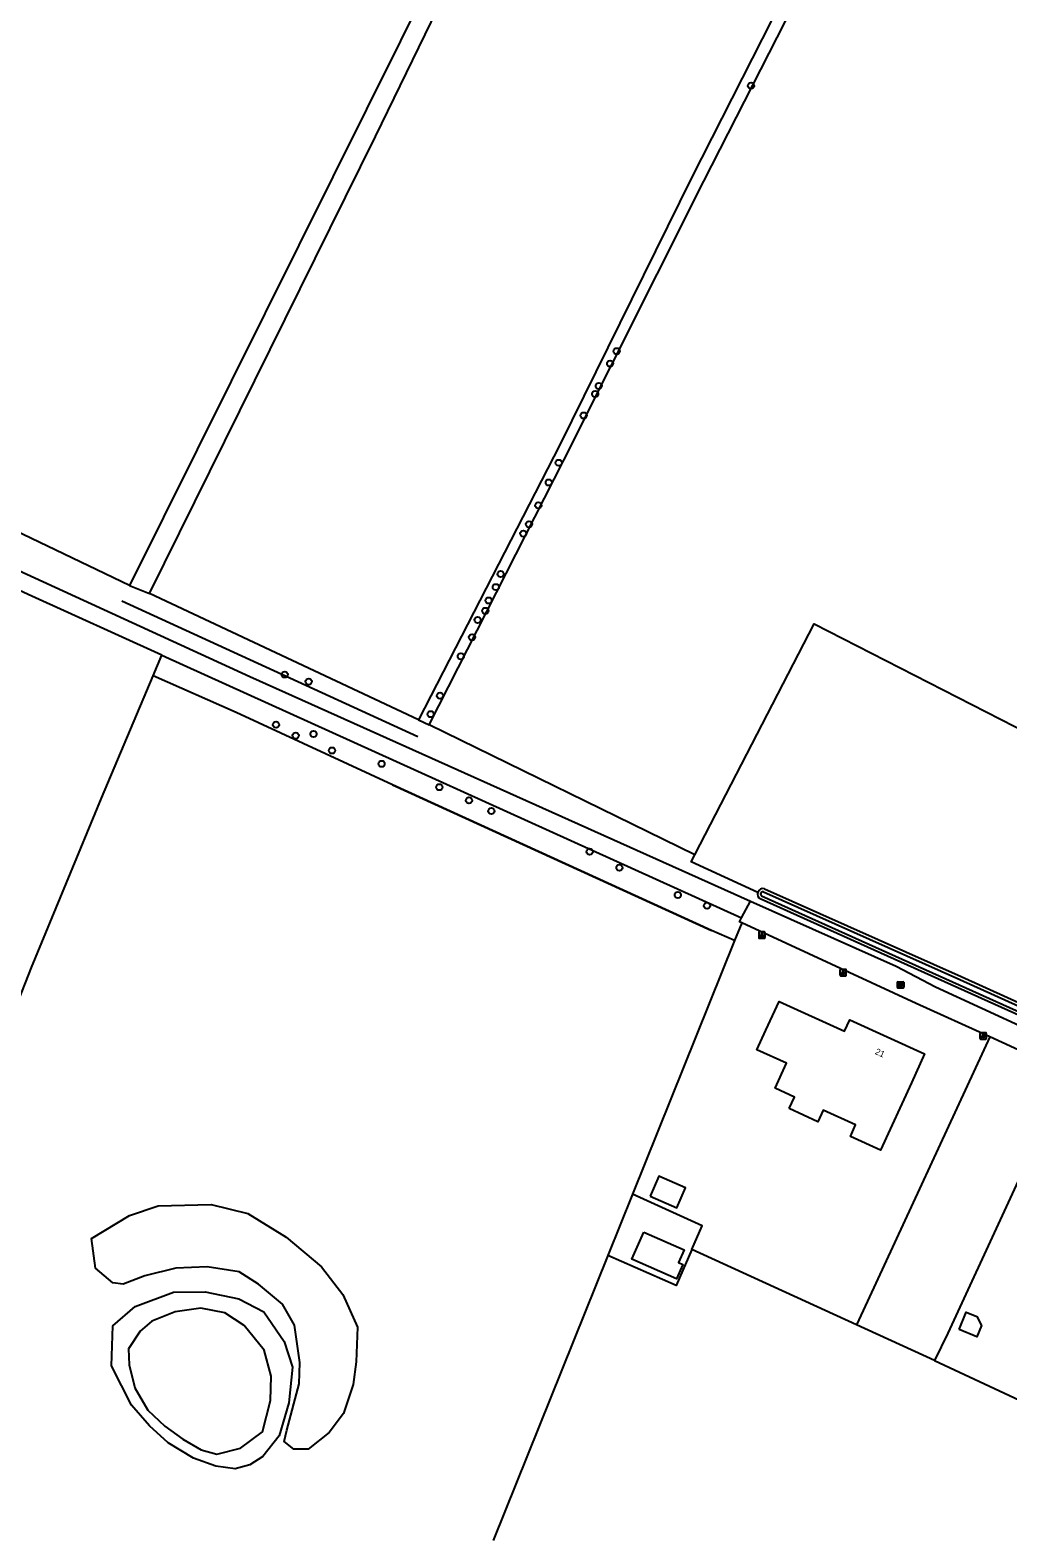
# Model space of a CAD drawing. Extents: x 155209 to 156823, y 385356 to 388482.
# Drawn here: x 155623.6 to 155777.4, y 385972.7 to 386210 of the extents above; entities that cross this region are included whole.
import ezdxf

# ---------------------------------------------------------------- set-up
doc = ezdxf.new("R2010")
doc.units = 0
for name, color, linetype in [('IMGEO_Boom', 7, 'Continuous'), ('IMGEO_Bouwland', 7, 'Continuous'), ('IMGEO_Grasland_agrarisch', 7, 'Continuous'), ('IMGEO_Grasland_overig', 7, 'Continuous'), ('IMGEO_Groenvoorziening', 7, 'Continuous'), ('IMGEO_Hek', 7, 'Continuous'), ('IMGEO_Houtwal', 7, 'Continuous'), ('IMGEO_Lichtpunt', 7, 'Continuous'), ('IMGEO_Loofbos', 7, 'Continuous'), ('IMGEO_Meer_plas_ven_vijver', 7, 'Continuous'), ('IMGEO_Pand', 7, 'Continuous'), ('IMGEO_Pand_nummerreeks', 7, 'Continuous'), ('IMGEO_Rijbaan_lokaal_open', 7, 'Continuous'), ('IMGEO_Rioolput', 7, 'Continuous'), ('IMGEO_Waterloop', 7, 'Continuous')]:
    doc.layers.add(name, color=color, linetype=linetype)

msp = doc.modelspace()

# ---------------------------------------------------------------- linework, layer by layer
at = {"layer": 'IMGEO_Boom'}
for centre in [(155737.01, 386201.25), (155715.85, 386159.47), (155714.83, 386157.52), (155713.05, 386154), (155712.48, 386152.72), (155710.67, 386149.34), (155706.75, 386141.9), (155705.18, 386138.8), (155703.53, 386135.19), (155701.19, 386130.76), (155702.06, 386132.22), (155697.6, 386124.38), (155696.85, 386122.33), (155695.19, 386118.6), (155695.7, 386120.23), (155693.97, 386117.17), (155693.11, 386114.44), (155691.34, 386111.45), (155663.63, 386108.57), (155667.4, 386107.46), (155688.06, 386105.24), (155686.57, 386102.34), (155662.25, 386100.67), (155668.15, 386099.23), (155665.35, 386098.96), (155671.06, 386096.62), (155678.86, 386094.52), (155687.95, 386090.85), (155692.62, 386088.76), (155696.15, 386087.09), (155711.61, 386080.69), (155716.3, 386078.17), (155725.49, 386073.86), (155730.09, 386072.18)]:
    msp.add_circle(centre, 0.489, dxfattribs=at)
at = {"layer": 'IMGEO_Bouwland'}
for points in [[(155639.2, 386122.59), (155606.88, 386138.08), (155552.95, 386161.21), (155559.66, 386175.91), (155576.44, 386207.57), (155574.39, 386208.21), (155571.97, 386208.45)], [(155684.67, 386101.45), (155642.36, 386121.35)], [(155728.14, 386080.19), (155686.33, 386100.64)]]:
    msp.add_lwpolyline(points, dxfattribs=at)
at = {"layer": 'IMGEO_Grasland_agrarisch'}
for points in [[(155714.46, 386017.11), (155696.41, 385972.27)], [(155753.63, 386006.21), (155727.71, 386018.1)], [(155765.9, 386000.59), (155785.57, 385991.44), (155812.34, 385978.74), (155809.88, 385972.63), (155808.05, 385968.03), (155801.87, 385953.41)]]:
    msp.add_lwpolyline(points, dxfattribs=at)
at = {"layer": 'IMGEO_Grasland_overig'}
for points in [[(155577.96, 386145.45), (155590.64, 386139.37), (155598.08, 386135.8), (155658.12, 386108.28), (155736.9, 386072.88)], [(155644.28, 386111.61), (155735.52, 386070.28)], [(155774.57, 386051.53), (155773.63, 386049.48), (155755.36, 386009.95), (155753.63, 386006.21)], [(155786.93, 386045.9), (155786.05, 386043.98), (155767.96, 386004.93), (155765.9, 386000.59)], [(155718.37, 386026.8), (155714.46, 386017.11)], [(155727.71, 386018.1), (155729.32, 386021.82), (155718.37, 386026.8)], [(155727.71, 386018.1), (155725.24, 386012.39), (155714.46, 386017.11)], [(155765.9, 386000.59), (155753.63, 386006.21)]]:
    msp.add_lwpolyline(points, dxfattribs=at)
at = {"layer": 'IMGEO_Groenvoorziening'}
for points in [[(155734.42, 386066.69), (155730.79, 386068.29), (155680.57, 386091.23), (155655.98, 386102.58), (155642.9, 386108.36)], [(155807.53, 386042.14), (155738.44, 386073.25)], [(155735.55, 386069.49), (155734.42, 386066.69)], [(155734.42, 386066.69), (155718.37, 386026.8)], [(155660.16, 385985.51), (155658.12, 385984.21), (155655.81, 385983.53), (155652.78, 385983.95), (155649.29, 385985.26), (155645.26, 385987.65), (155642.36, 385990.3), (155639.5, 385993.56), (155636.36, 385999.79), (155636.59, 386006.08), (155640.11, 386009.09), (155646.11, 386011.35), (155651.1, 386011.4), (155656.42, 386010.29), (155660.34, 386008.25), (155663.53, 386003.59), (155664.87, 385999.56), (155664.27, 385993.97), (155662.74, 385988.75), (155660.16, 385985.51)]]:
    msp.add_lwpolyline(points, dxfattribs=at)
msp.add_arc((155738.9, 386074), 0.881, 161.5794, 238.3689, dxfattribs=at)
at = {"layer": 'IMGEO_Hek'}
for points in [[(155637.98, 386120.16), (155684.58, 386098.82)], [(155728.14, 386080.19), (155746.94, 386116.53)], [(155680.57, 386091.23), (155655.98, 386102.58), (155642.9, 386108.36)], [(155680.57, 386091.23), (155730.79, 386068.29)], [(155734.42, 386066.69), (155730.79, 386068.29)]]:
    msp.add_lwpolyline(points, dxfattribs=at)
at = {"layer": 'IMGEO_Houtwal'}
for points in [[(155728.48, 386298.72), (155726.94, 386299.43), (155724.52, 386294.86), (155708.36, 386261.64), (155681.83, 386208.31), (155639.2, 386122.59)], [(155642.36, 386121.35), (155677.91, 386193.26), (155689.59, 386217.32), (155704.36, 386246.76), (155708.82, 386256.23), (155729.99, 386297.98), (155728.48, 386298.72)], [(155776.23, 386279.85), (155775.47, 386280.18), (155753.06, 386236.87), (155727.66, 386186.74), (155706.93, 386144.74), (155684.67, 386101.45)], [(155686.33, 386100.64), (155707.56, 386142.3), (155729.56, 386186.22), (155777.11, 386279.38), (155776.23, 386279.85)], [(155639.2, 386122.59), (155642.36, 386121.35)], [(155684.67, 386101.45), (155686.33, 386100.64)]]:
    msp.add_lwpolyline(points, dxfattribs=at)
at = {"layer": 'IMGEO_Lichtpunt'}
for p, q in [((155738.21, 386067.96), (155738.21, 386067.16)), ((155738.21, 386067.96), (155738.21, 386067.16)), ((155739.11, 386068.06), (155738.31, 386068.06)), ((155739.11, 386068.06), (155738.31, 386068.06)), ((155738.31, 386067.06), (155739.11, 386067.06)), ((155738.31, 386067.06), (155739.11, 386067.06)), ((155739.21, 386067.16), (155739.21, 386067.96)), ((155739.21, 386067.16), (155739.21, 386067.96)), ((155751.01, 386062.06), (155751.01, 386061.25)), ((155751.01, 386062.06), (155751.01, 386061.25)), ((155751.91, 386062.15), (155751.1, 386062.15)), ((155751.91, 386062.15), (155751.1, 386062.15)), ((155752, 386061.25), (155752, 386062.06)), ((155752, 386061.25), (155752, 386062.06)), ((155751.1, 386061.16), (155751.91, 386061.16)), ((155751.1, 386061.16), (155751.91, 386061.16)), ((155773.94, 386052.18), (155773.14, 386052.18)), ((155773.94, 386052.18), (155773.14, 386052.18)), ((155773.04, 386052.09), (155773.04, 386051.28)), ((155773.04, 386052.09), (155773.04, 386051.28)), ((155773.14, 386051.18), (155773.94, 386051.18)), ((155773.14, 386051.18), (155773.94, 386051.18)), ((155774.04, 386051.28), (155774.04, 386052.09)), ((155774.04, 386051.28), (155774.04, 386052.09))]:
    msp.add_line(p, q, dxfattribs=at)
for points in [[(155738.59, 386067.63), (155738.63, 386067.6), (155738.44, 386067.34), (155738.4, 386067.36), (155738.59, 386067.63)], [(155738.69, 386067.58), (155738.74, 386067.58), (155738.74, 386067.26), (155738.69, 386067.26), (155738.69, 386067.58)], [(155738.8, 386067.6), (155738.84, 386067.63), (155739.02, 386067.36), (155738.99, 386067.34), (155738.8, 386067.6)], [(155751.38, 386061.72), (155751.42, 386061.69), (155751.23, 386061.43), (155751.19, 386061.46), (155751.38, 386061.72)], [(155751.48, 386061.67), (155751.53, 386061.67), (155751.53, 386061.35), (155751.48, 386061.35), (155751.48, 386061.67)], [(155751.59, 386061.69), (155751.63, 386061.72), (155751.82, 386061.46), (155751.78, 386061.43), (155751.59, 386061.69)], [(155773.42, 386051.75), (155773.45, 386051.72), (155773.27, 386051.46), (155773.23, 386051.49), (155773.42, 386051.75)], [(155773.52, 386051.7), (155773.56, 386051.7), (155773.56, 386051.38), (155773.52, 386051.38), (155773.52, 386051.7)], [(155773.63, 386051.72), (155773.67, 386051.75), (155773.85, 386051.49), (155773.81, 386051.46), (155773.63, 386051.72)]]:
    msp.add_lwpolyline(points, dxfattribs=at)
for centre in [(155738.71, 386067.76), (155751.51, 386061.86), (155773.54, 386051.88)]:
    msp.add_circle(centre, 0.0994, dxfattribs=at)
for centre, start, end in [((155738.31, 386067.96), 90, 180), ((155738.31, 386067.96), 90, 180), ((155738.31, 386067.16), 180, 270), ((155738.31, 386067.16), 180, 270), ((155739.11, 386067.96), 0, 90), ((155739.11, 386067.96), 0, 90), ((155739.11, 386067.16), 270, 0), ((155739.11, 386067.16), 270, 360), ((155751.1, 386062.06), 90, 180), ((155751.1, 386062.06), 90, 180), ((155751.91, 386062.06), 0, 90), ((155751.91, 386062.06), 0, 90), ((155751.1, 386061.25), 180, 270), ((155751.1, 386061.25), 180, 270), ((155751.91, 386061.25), 270, 0), ((155751.91, 386061.25), 270, 360), ((155773.14, 386052.09), 90, 180), ((155773.14, 386052.09), 90, 180), ((155773.94, 386052.09), 0, 90), ((155773.94, 386052.09), 0, 90), ((155773.14, 386051.28), 180, 270), ((155773.14, 386051.28), 180, 270), ((155773.94, 386051.28), 270, 0), ((155773.94, 386051.28), 270, 360)]:
    msp.add_arc(centre, 0.0946, start, end, dxfattribs=at)
at = {"layer": 'IMGEO_Loofbos'}
for points in [[(155644.28, 386111.61), (155623.23, 386121.15), (155590.17, 386136.48)], [(155728.14, 386080.19), (155746.94, 386116.53), (155834.92, 386071.53)], [(155642.9, 386108.36), (155644.28, 386111.61)], [(155600.72, 386002.52), (155612.62, 386034.06), (155623.77, 386062.46), (155634.78, 386089.14), (155642.9, 386108.36)], [(155738.07, 386074.28), (155727.58, 386079.11), (155728.14, 386080.19)], [(155739.12, 386074.85), (155770.1, 386061.03), (155808.28, 386043.75)], [(155643.73, 386024.97), (155652.02, 386025.17), (155657.79, 386023.76), (155663.86, 386020.01), (155669.42, 386015.36), (155672.75, 386011.01), (155675.08, 386005.85), (155674.88, 386000.39), (155674.37, 385996.84), (155672.85, 385992.29), (155670.63, 385989.26), (155667.29, 385986.63), (155665.07, 385986.63), (155663.55, 385987.84), (155663.96, 385989.66), (155665.88, 385996.95), (155665.98, 386000.28), (155665.17, 386006.15), (155663.25, 386009.49), (155659.51, 386012.63), (155656.47, 386014.55), (155651.42, 386015.36), (155646.46, 386015.16), (155641.61, 386013.94), (155638.19, 386012.64), (155636.56, 386012.83), (155633.83, 386015.16), (155633.22, 386019.81), (155639.18, 386023.45), (155643.73, 386024.97)]]:
    msp.add_lwpolyline(points, dxfattribs=at)
msp.add_arc((155738.9, 386074), 0.879, 75.7492, 161.4105, dxfattribs=at)
at = {"layer": 'IMGEO_Meer_plas_ven_vijver'}
msp.add_lwpolyline([(155652.95, 385985.88), (155656.66, 385986.82), (155660.13, 385989.36), (155661.38, 385994.3), (155661.51, 385998.14), (155660.36, 386002.25), (155657.26, 386006.09), (155654.21, 386008.12), (155650.43, 386008.82), (155646.36, 386008.26), (155642.71, 386006.78), (155640.89, 386005.23), (155639.01, 386002.45), (155639.15, 385999.9), (155640.03, 385996.29), (155642.1, 385992.78), (155644.74, 385990.27), (155647.61, 385988.2), (155650.47, 385986.56), (155652.95, 385985.88)], dxfattribs=at)
at = {"layer": 'IMGEO_Pand'}
for points in [[(155743, 386040.26), (155743.83, 386042.08), (155740.8, 386043.46), (155742.57, 386047.38), (155737.92, 386049.5), (155739.33, 386052.58), (155741.41, 386057.13), (155751.74, 386052.44), (155752.57, 386054.25), (155764.33, 386048.88), (155762.26, 386044.33), (155757.4, 386033.69), (155752.64, 386035.86), (155753.47, 386037.68), (155748.37, 386040.01), (155747.54, 386038.19), (155743, 386040.26)], [(155721.12, 386026.45), (155725.31, 386024.62), (155726.68, 386027.78), (155722.5, 386029.61), (155721.12, 386026.45)], [(155720.14, 386020.83), (155726.48, 386018.02), (155725.6, 386016.02), (155726.28, 386015.72), (155725.28, 386013.44), (155718.25, 386016.55), (155720.14, 386020.83)], [(155769.75, 386005.48), (155770.87, 386008.2), (155772.55, 386007.51), (155773.26, 386006.1), (155772.53, 386004.34), (155769.75, 386005.48)]]:
    msp.add_lwpolyline(points, dxfattribs=at)
at = {"layer": 'IMGEO_Rijbaan_lokaal_open'}
for points in [[(155735.52, 386070.28), (155736.9, 386072.88)], [(155736.9, 386072.88), (155759.83, 386062.69), (155766.03, 386059.41), (155780.61, 386052.71), (155832.25, 386029.22), (155834.86, 386028.6), (155915.05, 385991.74)], [(155735.55, 386069.49), (155735.2, 386069.65), (155735.52, 386070.28)], [(155774.57, 386051.53), (155763.02, 386056.8), (155735.55, 386069.49)], [(155786.93, 386045.9), (155774.57, 386051.53)]]:
    msp.add_lwpolyline(points, dxfattribs=at)
at = {"layer": 'IMGEO_Rioolput'}
for p, q in [((155760.05, 386059.31), (155760.05, 386060.16)), ((155760.12, 386060.23), (155760.98, 386060.23)), ((155760.98, 386059.23), (155760.12, 386059.23)), ((155760.56, 386059.45), (155760.53, 386059.45)), ((155760.54, 386060.01), (155760.56, 386060.01)), ((155761.05, 386060.16), (155761.05, 386059.31))]:
    msp.add_line(p, q, dxfattribs=at)
for points in [[(155760.05, 386059.31), (155760.05, 386060.16)], [(155760.12, 386060.23), (155760.98, 386060.23)], [(155760.98, 386059.23), (155760.12, 386059.23)], [(155760.64, 386059.93), (155760.38, 386059.93), (155760.38, 386059.53)], [(155760.38, 386059.53), (155760.51, 386059.53), (155760.51, 386059.7), (155760.52, 386059.7)], [(155760.56, 386059.85), (155760.51, 386059.85), (155760.51, 386059.77)], [(155760.51, 386059.77), (155760.56, 386059.77)], [(155760.57, 386059.67), (155760.64, 386059.53), (155760.78, 386059.53), (155760.71, 386059.66)], [(155761.05, 386060.16), (155761.05, 386059.31)]]:
    msp.add_lwpolyline(points, dxfattribs=at)
for centre, radius, start, end in [((155760.12, 386060.16), 0.0765, 91.552, 178.448), ((155760.12, 386060.16), 0.0765, 91.552, 178.448), ((155760.12, 386059.31), 0.0765, 181.552, 268.448), ((155760.12, 386059.31), 0.0765, 181.552, 268.448), ((155760.52, 386059.64), 0.0533, 26.0293, 88.6989), ((155760.57, 386059.76), 0.0964, 77.0061, 93.1865), ((155760.55, 386059.96), 0.19, 274.7715, 282.9687), ((155760.58, 386059.81), 0.0378, 276.6634, 79.6772), ((155760.64, 386059.82), 0.109, 350.3612, 89.416), ((155760.63, 386059.82), 0.112, 277.5842, 350.9817), ((155760.62, 386059.61), 0.108, 29.5134, 73.7905), ((155760.97, 386060.16), 0.0765, 1.552, 88.448), ((155760.97, 386060.16), 0.0765, 1.552, 88.448), ((155760.97, 386059.31), 0.0765, 271.552, 358.448), ((155760.97, 386059.31), 0.0765, 271.552, 358.448)]:
    msp.add_arc(centre, radius, start, end, dxfattribs=at)
for centre, major_axis, ratio, start_param, end_param in [((155760.54, 386059.73), (-0.387, 0.002), 0.722429, 4.712389, 7.853982), ((155760.56, 386059.73), (-0.39, 0.002), 0.717154, 1.570796, 4.712389)]:
    msp.add_ellipse(centre, major_axis=major_axis, ratio=ratio, start_param=start_param, end_param=end_param, dxfattribs=at)
at = {"layer": 'IMGEO_Waterloop'}
for points in [[(155807.73, 386042.6), (155738.68, 386073.7)], [(155738.96, 386074.38), (155769.89, 386060.57), (155808.06, 386043.3)]]:
    msp.add_lwpolyline(points, dxfattribs=at)
msp.add_arc((155738.9, 386074), 0.377, 80.8048, 234.7824, dxfattribs=at)

# ---------------------------------------------------------------- texts
at = {"layer": 'IMGEO_Pand_nummerreeks'}
msp.add_text('21', height=1, rotation=335.4768, dxfattribs=at).set_placement((155756.44, 386048.88))

doc.saveas('drawing.dxf')
